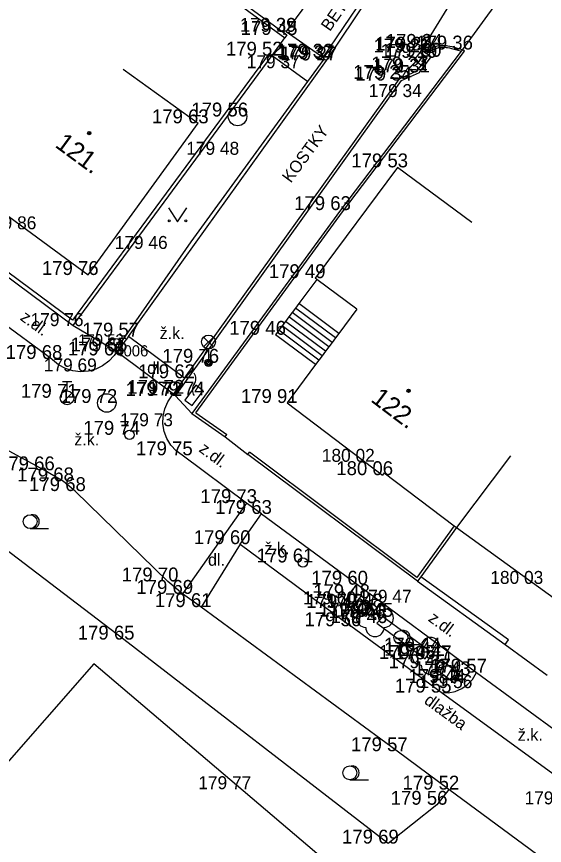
# Model space of a CAD drawing. Extents: x -537755 to -537431, y -1180722 to -1180510.
# Drawn here: x -537587.28 to -537558.74, y -1180628.73 to -1180583.92 of the extents above; entities that cross this region are included whole.
import ezdxf

# ---------------------------------------------------------------- set-up
doc = ezdxf.new("R2010")
doc.units = 0
for name, color, linetype in [('Vrstva 1', 7, 'Continuous'), ('Vrstva 10', 7, 'Continuous'), ('Vrstva 11', 7, 'Continuous'), ('Vrstva 21', 7, 'Continuous'), ('Vrstva 22', 7, 'Continuous'), ('Vrstva 23', 7, 'Continuous'), ('Vrstva 24', 7, 'Continuous'), ('Vrstva 27', 7, 'Continuous'), ('Vrstva 28', 7, 'Continuous'), ('Vrstva 3', 7, 'Continuous'), ('Vrstva 33', 7, 'Continuous'), ('Vrstva 36', 7, 'Continuous'), ('Vrstva 39', 7, 'Continuous'), ('Vrstva 40', 7, 'Continuous'), ('Vrstva 47', 7, 'Continuous'), ('Vrstva 5', 7, 'Continuous'), ('Vrstva 7', 7, 'Continuous'), ('Vrstva 8', 7, 'Continuous')]:
    doc.layers.add(name, color=color, linetype=linetype)

msp = doc.modelspace()

# ---------------------------------------------------------------- linework, layer by layer
at = {"layer": 'Vrstva 1'}
for p, q in [((-537572.71, -1180584.74), (-537572.71, -1180584.74)), ((-537572.66, -1180584.91), (-537572.66, -1180584.91)), ((-537573.46, -1180586.03), (-537573.46, -1180586.03)), ((-537565.48, -1180585.86), (-537565.48, -1180585.86)), ((-537565.39, -1180585.76), (-537565.39, -1180585.76)), ((-537564.82, -1180585.61), (-537564.82, -1180585.61)), ((-537563.17, -1180585.7), (-537563.17, -1180585.7)), ((-537570.72, -1180586.14), (-537570.72, -1180586.14)), ((-537570.65, -1180586.23), (-537570.65, -1180586.23)), ((-537570.52, -1180586.29), (-537570.52, -1180586.29)), ((-537565.1, -1180586.15), (-537565.1, -1180586.15)), ((-537564.87, -1180586.09), (-537564.87, -1180586.09)), ((-537572.5, -1180586.71), (-537572.5, -1180586.71)), ((-537565.6, -1180586.83), (-537565.6, -1180586.83)), ((-537565.5, -1180586.94), (-537565.5, -1180586.94)), ((-537566.58, -1180587.29), (-537566.58, -1180587.29)), ((-537566.47, -1180587.38), (-537566.47, -1180587.38)), ((-537565.9, -1180588.27), (-537565.9, -1180588.27)), ((-537575.33, -1180589.32), (-537575.33, -1180589.32)), ((-537577.46, -1180589.69), (-537577.46, -1180589.69)), ((-537575.77, -1180591.39), (-537575.77, -1180591.39)), ((-537566.78, -1180591.89), (-537566.78, -1180591.89)), ((-537566.68, -1180592.07), (-537566.68, -1180592.07)), ((-537569.77, -1180594.38), (-537569.77, -1180594.38)), ((-537586.74, -1180595.42), (-537586.74, -1180595.42)), ((-537579.64, -1180596.48), (-537579.64, -1180596.48)), ((-537583.41, -1180597.89), (-537583.41, -1180597.89)), ((-537571.14, -1180598.06), (-537571.14, -1180598.06)), ((-537584.21, -1180600.62), (-537584.21, -1180600.62)), ((-537584.189, -1180600.653), (-537584.189, -1180600.653)), ((-537581.222, -1180601.219), (-537581.222, -1180601.219)), ((-537573.28, -1180601.12), (-537573.28, -1180601.12)), ((-537582, -1180601.81), (-537582, -1180601.81)), ((-537581.93, -1180601.9), (-537581.93, -1180601.9)), ((-537581.855, -1180602.02), (-537581.855, -1180602.02)), ((-537585.371, -1180602.432), (-537585.371, -1180602.432)), ((-537582.009, -1180602.238), (-537582.009, -1180602.238)), ((-537576.9, -1180602.62), (-537576.9, -1180602.62)), ((-537583, -1180602.82), (-537583, -1180602.82)), ((-537576.898, -1180602.635), (-537576.898, -1180602.635)), ((-537583.472, -1180603.103), (-537583.472, -1180603.103)), ((-537578.205, -1180603.471), (-537578.205, -1180603.471)), ((-537578.93, -1180604.22), (-537578.93, -1180604.22)), ((-537578.81, -1180604.32), (-537578.81, -1180604.32)), ((-537578.787, -1180604.314), (-537578.787, -1180604.314)), ((-537577.68, -1180604.4), (-537577.68, -1180604.4)), ((-537584.59, -1180604.58), (-537584.59, -1180604.58)), ((-537584.548, -1180604.527), (-537584.548, -1180604.527)), ((-537582.401, -1180604.81), (-537582.401, -1180604.81)), ((-537582.4, -1180604.65), (-537582.4, -1180604.65)), ((-537578.879, -1180604.43), (-537578.879, -1180604.43)), ((-537572.65, -1180604.81), (-537572.65, -1180604.81)), ((-537577.83, -1180605.13), (-537577.83, -1180605.13)), ((-537577.8, -1180605.38), (-537577.8, -1180605.38)), ((-537579.354, -1180606.065), (-537579.354, -1180606.065)), ((-537581.171, -1180606.53), (-537581.171, -1180606.53)), ((-537576, -1180606.64), (-537576, -1180606.64)), ((-537578.323, -1180607.637), (-537578.323, -1180607.637)), ((-537574.77, -1180607.59), (-537574.77, -1180607.59)), ((-537568.44, -1180607.99), (-537568.44, -1180607.99)), ((-537585.782, -1180608.449), (-537585.782, -1180608.449)), ((-537567.49, -1180608.71), (-537567.49, -1180608.71)), ((-537584.746, -1180609.048), (-537584.746, -1180609.048)), ((-537584.102, -1180609.571), (-537584.102, -1180609.571)), ((-537574.844, -1180610.221), (-537574.844, -1180610.221)), ((-537574.041, -1180610.808), (-537574.041, -1180610.808)), ((-537575.196, -1180612.441), (-537575.196, -1180612.441)), ((-537571.797, -1180613.431), (-537571.797, -1180613.431)), ((-537579.093, -1180614.456), (-537579.093, -1180614.456)), ((-537568.847, -1180614.632), (-537568.847, -1180614.632)), ((-537565.6, -1180614.45), (-537565.6, -1180614.45)), ((-537559.33, -1180614.59), (-537559.33, -1180614.59)), ((-537578.3, -1180615.128), (-537578.3, -1180615.128)), ((-537568.74, -1180615.36), (-537568.74, -1180615.36)), ((-537566.45, -1180615.61), (-537566.45, -1180615.61)), ((-537577.305, -1180615.844), (-537577.305, -1180615.844)), ((-537569.459, -1180615.692), (-537569.459, -1180615.692)), ((-537569.12, -1180615.89), (-537569.12, -1180615.89)), ((-537568.03, -1180615.87), (-537568.03, -1180615.87)), ((-537568.42, -1180616.36), (-537568.42, -1180616.36)), ((-537567.9, -1180616.44), (-537567.9, -1180616.44)), ((-537567.48, -1180616.37), (-537567.48, -1180616.37)), ((-537569.213, -1180616.879), (-537569.213, -1180616.879)), ((-537567.8, -1180616.71), (-537567.8, -1180616.71)), ((-537581.47, -1180617.6), (-537581.47, -1180617.6)), ((-537560.86, -1180617.86), (-537560.86, -1180617.86)), ((-537564.91, -1180618.25), (-537564.91, -1180618.25)), ((-537565.19, -1180618.65), (-537565.19, -1180618.65)), ((-537564.9, -1180618.48), (-537564.9, -1180618.48)), ((-537564.33, -1180618.67), (-537564.33, -1180618.67)), ((-537564.66, -1180619.15), (-537564.66, -1180619.15)), ((-537563.29, -1180619.53), (-537563.29, -1180619.53)), ((-537562.417, -1180619.388), (-537562.417, -1180619.388)), ((-537563.59, -1180619.95), (-537563.59, -1180619.95)), ((-537564.327, -1180620.468), (-537564.327, -1180620.468)), ((-537563.163, -1180620.224), (-537563.163, -1180620.224)), ((-537566.699, -1180623.637), (-537566.699, -1180623.637)), ((-537575.12, -1180625.69), (-537575.12, -1180625.69)), ((-537563.91, -1180625.71), (-537563.91, -1180625.71)), ((-537564.55, -1180626.53), (-537564.55, -1180626.53)), ((-537567.18, -1180628.63), (-537567.18, -1180628.63))]:
    msp.add_line(p, q, dxfattribs=at)
at = {"layer": 'Vrstva 10'}
for p, q in [((-537565.39, -1180585.76), (-537561.54, -1180579.49)), ((-537570.52, -1180586.29), (-537567.1, -1180581.19)), ((-537565.48, -1180585.86), (-537565.39, -1180585.76)), ((-537581.222, -1180601.219), (-537570.52, -1180586.29)), ((-537578.205, -1180603.471), (-537566.58, -1180587.29)), ((-537585.371, -1180602.432), (-537588.373, -1180600.246)), ((-537581.222, -1180601.219), (-537581.855, -1180602.02)), ((-537578.205, -1180603.471), (-537581.222, -1180601.219)), ((-537581.855, -1180602.02), (-537582.009, -1180602.238)), ((-537581.855, -1180602.02), (-537578.787, -1180604.314)), ((-537578.205, -1180603.471), (-537578.787, -1180604.314)), ((-537578.879, -1180604.43), (-537578.787, -1180604.314)), ((-537585.782, -1180608.449), (-537591.895, -1180605.124)), ((-537574.844, -1180610.221), (-537578.323, -1180607.637)), ((-537579.093, -1180614.456), (-537584.102, -1180609.571)), ((-537574.844, -1180610.221), (-537578.3, -1180615.128)), ((-537574.041, -1180610.808), (-537574.844, -1180610.221)), ((-537575.196, -1180612.441), (-537574.041, -1180610.808)), ((-537574.041, -1180610.808), (-537568.847, -1180614.632)), ((-537575.196, -1180612.441), (-537577.305, -1180615.844)), ((-537575.196, -1180612.441), (-537569.213, -1180616.879)), ((-537578.3, -1180615.128), (-537579.093, -1180614.456)), ((-537577.305, -1180615.844), (-537578.3, -1180615.128)), ((-537566.699, -1180623.637), (-537577.305, -1180615.844)), ((-537564.327, -1180620.468), (-537569.213, -1180616.879)), ((-537562.417, -1180619.388), (-537555.435, -1180624.491)), ((-537556.21, -1180626.37), (-537564.327, -1180620.468)), ((-537563.91, -1180625.71), (-537566.699, -1180623.637)), ((-537558.407, -1180629.756), (-537563.91, -1180625.71))]:
    msp.add_line(p, q, dxfattribs=at)
for points in [[(-537565.225, -1180585.865), (-537565.057, -1180585.747), (-537565, -1180585.71), (-537564.912, -1180585.658), (-537564.82, -1180585.61), (-537564.755, -1180585.58), (-537564.693, -1180585.556), (-537564.634, -1180585.537), (-537564.579, -1180585.521), (-537564.527, -1180585.508), (-537564.428, -1180585.49), (-537564.341, -1180585.48), (-537564.265, -1180585.475), (-537564.198, -1180585.475), (-537564.14, -1180585.476), (-537564.038, -1180585.484), (-537563.962, -1180585.493), (-537563.85, -1180585.514), (-537563.74, -1180585.541), (-537563.455, -1180585.62), (-537563.17, -1180585.7)], [(-537566.58, -1180587.29), (-537565.6, -1180586.83), (-537565.1, -1180586.15), (-537565.48, -1180585.86)], [(-537582.009, -1180602.238), (-537582.29, -1180602.549), (-537582.624, -1180602.8), (-537583.001, -1180602.984), (-537583.405, -1180603.093), (-537583.823, -1180603.123), (-537584.238, -1180603.073), (-537584.637, -1180602.946), (-537585.004, -1180602.745), (-537585.327, -1180602.478), (-537585.371, -1180602.432)], [(-537578.323, -1180607.637), (-537578.656, -1180607.393), (-537578.937, -1180607.089), (-537579.153, -1180606.736), (-537579.298, -1180606.349), (-537579.366, -1180605.941), (-537579.354, -1180605.528), (-537579.263, -1180605.125), (-537579.096, -1180604.747), (-537578.879, -1180604.43)], [(-537584.102, -1180609.571), (-537584.746, -1180609.048), (-537585.782, -1180608.449)], [(-537569.213, -1180616.879), (-537569.376, -1180616.548), (-537569.465, -1180616.189), (-537569.474, -1180615.82), (-537569.404, -1180615.457), (-537569.258, -1180615.118), (-537569.042, -1180614.818), (-537568.847, -1180614.632)], [(-537564.327, -1180620.468), (-537563.943, -1180620.474), (-537563.566, -1180620.401), (-537563.212, -1180620.252), (-537562.897, -1180620.033), (-537562.634, -1180619.753), (-537562.417, -1180619.388)]]:
    msp.add_lwpolyline(points, dxfattribs=at)
at = {"layer": 'Vrstva 11'}
for p, q in [((-537567.3, -1180581.08), (-537570.72, -1180586.14)), ((-537573.46, -1180586.03), (-537571.528, -1180587.436)), ((-537578.691, -1180604.418), (-537566.47, -1180587.38)), ((-537569.852, -1180601.053), (-537572.025, -1180599.435)), ((-537570.211, -1180601.534), (-537572.384, -1180599.916)), ((-537570.032, -1180601.294), (-537572.205, -1180599.676)), ((-537570.39, -1180601.775), (-537572.563, -1180600.157)), ((-537570.748, -1180602.256), (-537572.921, -1180600.638)), ((-537570.569, -1180602.016), (-537572.742, -1180600.398)), ((-537571.107, -1180602.738), (-537573.28, -1180601.12)), ((-537570.927, -1180602.497), (-537573.1, -1180600.879)), ((-537568.847, -1180614.632), (-537562.417, -1180619.388)), ((-537583.093, -1180618.912), (-537593.47, -1180630.74)), ((-537568.58, -1180631.25), (-537583.093, -1180618.912))]:
    msp.add_line(p, q, dxfattribs=at)
for points in [[(-537570.72, -1180586.14), (-537572.71, -1180584.74), (-537570.658, -1180581.969)], [(-537565.133, -1180585.923), (-537565.001, -1180585.83), (-537564.947, -1180585.795), (-537564.863, -1180585.745), (-537564.776, -1180585.7), (-537564.716, -1180585.672), (-537564.66, -1180585.65), (-537564.605, -1180585.633), (-537564.553, -1180585.618), (-537564.506, -1180585.606), (-537564.413, -1180585.589), (-537564.332, -1180585.58), (-537564.262, -1180585.575), (-537564.199, -1180585.575), (-537564.145, -1180585.576), (-537564.048, -1180585.584), (-537563.977, -1180585.592), (-537563.871, -1180585.612), (-537563.765, -1180585.638), (-537563.482, -1180585.716), (-537563.235, -1180585.785)], [(-537566.47, -1180587.38), (-537565.5, -1180586.94), (-537564.87, -1180586.09), (-537565.133, -1180585.923), (-537565.225, -1180585.865), (-537565.39, -1180585.76)], [(-537571.528, -1180587.436), (-537570.65, -1180586.23)], [(-537570.72, -1180586.14), (-537570.65, -1180586.23), (-537570.52, -1180586.29)], [(-537577.837, -1180596.095), (-537571.528, -1180587.436)], [(-537581.926, -1180601.978), (-537577.837, -1180596.095)], [(-537571.051, -1180598.126), (-537572.025, -1180599.435), (-537572.205, -1180599.676), (-537572.384, -1180599.916), (-537572.563, -1180600.157), (-537572.742, -1180600.398), (-537572.921, -1180600.638), (-537573.1, -1180600.879), (-537573.28, -1180601.12)], [(-537584.21, -1180600.62), (-537581.926, -1180601.978), (-537581.855, -1180602.02)], [(-537577.8, -1180605.38), (-537578.691, -1180604.418), (-537578.787, -1180604.314)]]:
    msp.add_lwpolyline(points, dxfattribs=at)
at = {"layer": 'Vrstva 21'}
for p, q in [((-537581.47, -1180617.6), (-537593.01, -1180608.83)), ((-537567.18, -1180628.63), (-537581.47, -1180617.6))]:
    msp.add_line(p, q, dxfattribs=at)
for points in [[(-537568.74, -1180615.36), (-537568.03, -1180615.87), (-537568.42, -1180616.36), (-537569.12, -1180615.89), (-537568.74, -1180615.36)], [(-537567.48, -1180616.37), (-537567.8, -1180616.71), (-537565.19, -1180618.65), (-537564.91, -1180618.25), (-537567.48, -1180616.37)], [(-537564.66, -1180619.15), (-537563.59, -1180619.95), (-537563.29, -1180619.53), (-537564.33, -1180618.67), (-537564.66, -1180619.15)], [(-537563.91, -1180625.71), (-537564.55, -1180626.53), (-537567.18, -1180628.63)]]:
    msp.add_lwpolyline(points, dxfattribs=at)
for radius in [0.375, 0.05]:
    msp.add_circle((-537581.94, -1180601.69), radius, dxfattribs=at)
at = {"layer": 'Vrstva 22'}
for centre in [(-537567.9, -1180616.44), (-537564.9, -1180618.48)]:
    msp.add_circle(centre, 0.05, dxfattribs=at)
for centre, start, end in [((-537567.9, -1180615.94), 0, 180), ((-537568.4, -1180616.44), 90, 270), ((-537567.4, -1180616.44), 270, 90), ((-537567.9, -1180616.94), 180, 0), ((-537564.9, -1180617.98), 0, 180), ((-537565.4, -1180618.48), 90, 270), ((-537564.4, -1180618.48), 270, 90), ((-537564.9, -1180618.98), 180, 0)]:
    msp.add_arc(centre, 0.5, start, end, dxfattribs=at)
at = {"layer": 'Vrstva 24'}
msp.add_lwpolyline([(-537577.776, -1180604.951), (-537577.182, -1180604.146), (-537577.584, -1180603.849), (-537578.178, -1180604.654)], close=True, dxfattribs=at)
for centre, start, end in [((-537578.08, -1180603.501), 323.1301, 36.8699), ((-537577.28, -1180604.101), 143.1301, 216.8699)]:
    msp.add_arc(centre, 0.5, start, end, dxfattribs=at)
at = {"layer": 'Vrstva 27'}
msp.add_line((-537565.277, -1180586.009), (-537565.575, -1180586.411), dxfattribs=at)
msp.add_lwpolyline([(-537565.478, -1180585.86), (-537565.776, -1180586.262), (-537565.374, -1180586.56), (-537565.076, -1180586.158)], close=True, dxfattribs=at)
for centre in [(-537575.33, -1180589.32), (-537582.401, -1180604.81)]:
    msp.add_circle(centre, 0.5, dxfattribs=at)
at = {"layer": 'Vrstva 28'}
for p, q in [((-537584.798, -1180603.652), (-537584.298, -1180603.652)), ((-537584.548, -1180604.152), (-537584.548, -1180603.652)), ((-537584.806, -1180604.799), (-537584.276, -1180604.269))]:
    msp.add_line(p, q, dxfattribs=at)
for centre, radius in [((-537584.548, -1180604.527), 0.375), ((-537581.171, -1180606.53), 0.25), ((-537571.797, -1180613.431), 0.25)]:
    msp.add_circle(centre, radius, dxfattribs=at)
at = {"layer": 'Vrstva 33'}
for p, q in [((-537577.163, -1180601.775), (-537576.633, -1180601.245)), ((-537577.163, -1180601.245), (-537576.633, -1180601.775)), ((-537576.898, -1180601.885), (-537576.898, -1180602.635))]:
    msp.add_line(p, q, dxfattribs=at)
for centre, radius in [((-537576.898, -1180601.51), 0.375), ((-537576.898, -1180602.635), 0.2), ((-537576.898, -1180602.635), 0.145), ((-537576.898, -1180602.635), 0.0876)]:
    msp.add_circle(centre, radius, dxfattribs=at)
at = {"layer": 'Vrstva 36'}
for p, q in [((-537586.548, -1180611.599), (-537585.548, -1180611.599)), ((-537568.606, -1180616.231), (-537567.606, -1180616.231)), ((-537566.497, -1180617.86), (-537565.497, -1180617.86)), ((-537563.978, -1180619.766), (-537562.978, -1180619.766)), ((-537569.256, -1180625.181), (-537568.256, -1180625.181))]:
    msp.add_line(p, q, dxfattribs=at)
msp.add_lwpolyline([(-537579.071, -1180594.26), (-537578.571, -1180595.01), (-537578.071, -1180594.26)], dxfattribs=at)
for centre, radius in [((-537579.021, -1180594.96), 0.05), ((-537578.122, -1180594.96), 0.05), ((-537586.548, -1180611.224), 0.375), ((-537568.606, -1180615.856), 0.375), ((-537566.497, -1180617.485), 0.375), ((-537563.978, -1180619.391), 0.375), ((-537569.256, -1180624.806), 0.375)]:
    msp.add_circle(centre, radius, dxfattribs=at)
for centre in [(-537586.423, -1180611.224), (-537568.481, -1180615.856), (-537566.372, -1180617.485), (-537563.853, -1180619.391), (-537569.131, -1180624.806)]:
    msp.add_arc(centre, 0.375, 260.4059, 99.5941, dxfattribs=at)
at = {"layer": 'Vrstva 39'}
for centre, radius in [((-537583.347, -1180590.215), 0.09), ((-537583.347, -1180590.215), 0.0398), ((-537566.079, -1180604.147), 0.09), ((-537566.079, -1180604.147), 0.0398)]:
    msp.add_circle(centre, radius, dxfattribs=at)
at = {"layer": 'Vrstva 5'}
for p, q in [((-537581.507, -1180586.754), (-537577.46, -1180589.69)), ((-537583.41, -1180597.89), (-537577.46, -1180589.69)), ((-537566.68, -1180592.07), (-537571.14, -1180598.06)), ((-537562.67, -1180595.056), (-537566.68, -1180592.07)), ((-537590.97, -1180592.33), (-537583.41, -1180597.89)), ((-537571.051, -1180598.126), (-537571.14, -1180598.06)), ((-537568.878, -1180599.744), (-537571.051, -1180598.126)), ((-537568.878, -1180599.744), (-537569.852, -1180601.053)), ((-537569.852, -1180601.053), (-537570.032, -1180601.294)), ((-537570.211, -1180601.534), (-537570.39, -1180601.775)), ((-537570.032, -1180601.294), (-537570.211, -1180601.534)), ((-537570.569, -1180602.016), (-537570.748, -1180602.256)), ((-537570.39, -1180601.775), (-537570.569, -1180602.016)), ((-537570.927, -1180602.497), (-537571.107, -1180602.738)), ((-537570.748, -1180602.256), (-537570.927, -1180602.497)), ((-537571.107, -1180602.738), (-537572.65, -1180604.81)), ((-537572.65, -1180604.81), (-537567.49, -1180608.71)), ((-537560.565, -1180607.675), (-537563.49, -1180611.545)), ((-537567.399, -1180608.59), (-537567.49, -1180608.71)), ((-537567.399, -1180608.59), (-537563.609, -1180611.455)), ((-537563.609, -1180611.455), (-537563.49, -1180611.545)), ((-537563.49, -1180611.545), (-537555.484, -1180617.35))]:
    msp.add_line(p, q, dxfattribs=at)
at = {"layer": 'Vrstva 7'}
for p, q in [((-537575.45, -1180583.1), (-537572.779, -1180585.071)), ((-537573.621, -1180585.911), (-537584.252, -1180600.34)), ((-537569.65, -1180594.47), (-537563.051, -1180585.791)), ((-537584.252, -1180600.34), (-537592.501, -1180594.219)), ((-537569.77, -1180594.38), (-537577.8, -1180605.38)), ((-537577.589, -1180605.345), (-537569.65, -1180594.47)), ((-537584.21, -1180600.62), (-537579.807, -1180594.644)), ((-537577.589, -1180605.345), (-537575.914, -1180606.517)), ((-537565.632, -1180614.239), (-537574.68, -1180607.47)), ((-537563.609, -1180611.455), (-537565.632, -1180614.239)), ((-537560.685, -1180617.616), (-537565.424, -1180614.207))]:
    msp.add_line(p, q, dxfattribs=at)
for points in [[(-537575.331, -1180582.939), (-537572.66, -1180584.91), (-537572.779, -1180585.071)], [(-537579.807, -1180594.644), (-537573.46, -1180586.03)], [(-537573.46, -1180586.03), (-537573.621, -1180585.911)], [(-537563.235, -1180585.785), (-537569.77, -1180594.38)], [(-537563.051, -1180585.791), (-537563.17, -1180585.7), (-537563.235, -1180585.785)], [(-537592.62, -1180594.38), (-537584.21, -1180600.62)], [(-537577.8, -1180605.38), (-537576, -1180606.64), (-537575.914, -1180606.517)], [(-537574.77, -1180607.59), (-537574.68, -1180607.47)], [(-537565.6, -1180614.45), (-537574.77, -1180607.59)], [(-537563.49, -1180611.545), (-537565.424, -1180614.207), (-537565.6, -1180614.45)], [(-537565.6, -1180614.45), (-537560.86, -1180617.86)], [(-537560.86, -1180617.86), (-537560.685, -1180617.616)]]:
    msp.add_lwpolyline(points, dxfattribs=at)
at = {"layer": 'Vrstva 8'}
for p, q in [((-537561.19, -1180582.96), (-537563.17, -1180585.7)), ((-537573.46, -1180586.03), (-537572.779, -1180585.071)), ((-537576, -1180606.64), (-537574.77, -1180607.59)), ((-537560.86, -1180617.86), (-537558.59, -1180619.52))]:
    msp.add_line(p, q, dxfattribs=at)

# ---------------------------------------------------------------- texts
at = {"layer": 'Vrstva 22'}
msp.add_text('179.53 ', height=0.6, dxfattribs=at).set_placement((-537583.94, -1180601.69))
at = {"layer": 'Vrstva 23'}
msp.add_text('4006', height=0.6, dxfattribs=at).set_placement((-537581.94, -1180602.29))
at = {"layer": 'Vrstva 3'}
for s, height, p in [('179 39 ', 0.75, (-537575.21, -1180584.74)), ('179 45 ', 0.75, (-537575.16, -1180584.91)), ('179 21 ', 0.75, (-537567.98, -1180585.86)), ('179 32 ', 0.75, (-537567.89, -1180585.76)), ('179 34 ', 0.75, (-537567.32, -1180585.61)), ('179 36 ', 0.75, (-537565.67, -1180585.7)), ('179 52 ', 0.75, (-537575.96, -1180586.03)), ('179 32 ', 0.75, (-537573.22, -1180586.14)), ('179 37 ', 0.75, (-537573.15, -1180586.23)), ('179 27 ', 0.75, (-537573.02, -1180586.29)), ('179 19 ', 0.75, (-537567.6, -1180586.15)), ('179 30 ', 0.75, (-537567.37, -1180586.09)), ('179 37 ', 0.7, (-537574.834, -1180586.71)), ('179 21 ', 0.75, (-537568.1, -1180586.83)), ('179 31 ', 0.75, (-537568, -1180586.94)), ('179 25 ', 0.75, (-537569.08, -1180587.29)), ('179 34 ', 0.75, (-537568.97, -1180587.38)), ('179 34 ', 0.7, (-537568.234, -1180588.27)), ('179 56 ', 0.75, (-537577.83, -1180589.32)), ('179 63 ', 0.75, (-537579.96, -1180589.69)), ('179 48 ', 0.7, (-537578.104, -1180591.39)), ('179 53 ', 0.75, (-537569.18, -1180592.07)), ('179 63 ', 0.75, (-537572.27, -1180594.38)), ('179 86 ', 0.7, (-537589.073, -1180595.42)), ('179 46 ', 0.7, (-537581.973, -1180596.48)), ('179 76 ', 0.75, (-537585.91, -1180597.89)), ('179 49 ', 0.75, (-537573.64, -1180598.06)), ('179 76 ', 0.7, (-537586.522, -1180600.653)), ('179 46 ', 0.75, (-537575.78, -1180601.12)), ('179 57 ', 0.75, (-537583.722, -1180601.219)), ('179 65 ', 0.75, (-537584.355, -1180602.02)), ('179 68 ', 0.75, (-537587.871, -1180602.432)), ('179 66 ', 0.75, (-537584.509, -1180602.238)), ('179 76 ', 0.75, (-537579.398, -1180602.635)), ('179 69 ', 0.7, (-537585.805, -1180603.103)), ('179 62 ', 0.75, (-537580.705, -1180603.471)), ('179 71 ', 0.75, (-537587.048, -1180604.527)), ('179 72 ', 0.75, (-537581.379, -1180604.43)), ('179 72 ', 0.75, (-537581.287, -1180604.314)), ('179 74 ', 0.75, (-537580.18, -1180604.4)), ('179 72 ', 0.75, (-537584.901, -1180604.81)), ('179 91 ', 0.75, (-537575.15, -1180604.81)), ('179 73 ', 0.7, (-537581.687, -1180606.065)), ('179 74 ', 0.75, (-537583.671, -1180606.53)), ('179 75 ', 0.75, (-537580.823, -1180607.637)), ('180 02 ', 0.7, (-537570.774, -1180607.99)), ('179 66 ', 0.75, (-537588.282, -1180608.449)), ('180 06 ', 0.75, (-537569.99, -1180608.71)), ('179 68 ', 0.75, (-537587.246, -1180609.048)), ('179 68 ', 0.75, (-537586.602, -1180609.571)), ('179 73 ', 0.75, (-537577.344, -1180610.221)), ('179 63 ', 0.75, (-537576.541, -1180610.808)), ('179 60 ', 0.75, (-537577.696, -1180612.441)), ('179 61 ', 0.75, (-537574.297, -1180613.431)), ('179 70 ', 0.75, (-537581.593, -1180614.456)), ('179 60 ', 0.75, (-537571.347, -1180614.632)), ('180 03 ', 0.7, (-537561.664, -1180614.59)), ('179 69 ', 0.75, (-537580.8, -1180615.128)), ('179 48 ', 0.75, (-537571.24, -1180615.36)), ('179 61 ', 0.75, (-537579.805, -1180615.844)), ('179 60 ', 0.7, (-537571.792, -1180615.692)), ('179 47 ', 0.75, (-537571.62, -1180615.89)), ('179 48 ', 0.75, (-537570.53, -1180615.87)), ('179 47 ', 0.7, (-537568.783, -1180615.61)), ('179 46 ', 0.75, (-537570.92, -1180616.36)), ('179 45 ', 0.75, (-537569.98, -1180616.37)), ('179 46 ', 0.75, (-537570.4, -1180616.44)), ('179 46 ', 0.75, (-537570.3, -1180616.71)), ('179 56 ', 0.75, (-537571.713, -1180616.879)), ('179 65 ', 0.75, (-537583.97, -1180617.6)), ('179 44 ', 0.75, (-537567.41, -1180618.25)), ('179 44 ', 0.75, (-537567.4, -1180618.48)), ('179 45 ', 0.75, (-537567.69, -1180618.65)), ('179 47 ', 0.75, (-537566.83, -1180618.67)), ('179 45 ', 0.75, (-537567.16, -1180619.15)), ('179 57 ', 0.75, (-537564.917, -1180619.388)), ('179 44 ', 0.75, (-537566.09, -1180619.95)), ('179 43 ', 0.75, (-537565.79, -1180619.53)), ('179 56 ', 0.7, (-537565.496, -1180620.224)), ('179 55 ', 0.75, (-537566.827, -1180620.468)), ('179 57 ', 0.75, (-537569.199, -1180623.637)), ('179 77 ', 0.7, (-537577.453, -1180625.69)), ('179 52 ', 0.75, (-537566.41, -1180625.71)), ('179 56 ', 0.75, (-537567.05, -1180626.53)), ('179 44 ', 0.7, (-537559.813, -1180626.51)), ('179 69 ', 0.75, (-537569.68, -1180628.63))]:
    msp.add_text(s, height=height, dxfattribs=at).set_placement(p)
at = {"layer": 'Vrstva 40'}
for s, rotation, p in [('BETON', 54.9456, (-537570.339, -1180584.759)), ('KOSTKY', 53.6829, (-537572.451, -1180592.952)), ('z.dl.', 323.9386, (-537587.129, -1180600.286)), ('z.dl.', 323.3972, (-537577.466, -1180607.401)), ('z.dl.', 323.5112, (-537565.062, -1180616.561)), ('dlažba', 323.7821, (-537565.29, -1180621.007))]:
    msp.add_text(s, height=0.65, rotation=rotation, dxfattribs=at).set_placement(p)
for s, p in [('ž.k.', (-537579.542, -1180601.356)), ('dl.', (-537580.219, -1180603.235)), ('ž.k.', (-537584.159, -1180607.107)), ('ž.k.', (-537573.876, -1180612.988)), ('dl.', (-537576.927, -1180613.611)), ('ž.k.', (-537560.176, -1180623.068))]:
    msp.add_text(s, height=0.65, dxfattribs=at).set_placement(p)
at = {"layer": 'Vrstva 47'}
for s, rotation, p in [('121.', 323.6674, (-537585.25, -1180590.936)), ('122.', 322.9175, (-537568.177, -1180604.696))]:
    msp.add_text(s, height=1, rotation=rotation, dxfattribs=at).set_placement(p)

doc.saveas('drawing.dxf')
